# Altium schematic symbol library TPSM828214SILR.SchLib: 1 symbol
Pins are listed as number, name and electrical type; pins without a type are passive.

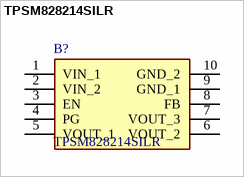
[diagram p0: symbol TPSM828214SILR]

## TPSM828214SILR
designator B?
Switching Voltage Regulators 5.5-V input, 1-A step-down module with integrated inductor in 2 x 2.5 x 1.1-mm SIP package; Manufacturer_Name: Texas Instruments; Geometry.Height: 1.1mm
footprint TPSM828214SILR
pins: 1 VIN_1, 2 VIN_2, 3 EN, 4 PG, 5 VOUT_1, 6 VOUT_2, 7 VOUT_3, 8 FB, 9 GND_1, 10 GND_2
